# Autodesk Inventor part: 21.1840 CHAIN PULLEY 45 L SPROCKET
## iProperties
Created: 2007-05
Part Number: 21.1840 CHAIN PULLEY 45 L SPROCKET
Document SubType Name: Modeling
Designer: Andy Moles
Material: Steel
Density: 7.85 g/cm^3
Mass: 21.5501 g
Surface Area: 17.9628 cm^2
Volume: 2.74523 cm^3
Author: Andy Moles
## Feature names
1. Extrusion1
2. Extrusion2
3. Circular Pattern1
4. Extrusion3
5. Extrusion4
6. Extrusion5
